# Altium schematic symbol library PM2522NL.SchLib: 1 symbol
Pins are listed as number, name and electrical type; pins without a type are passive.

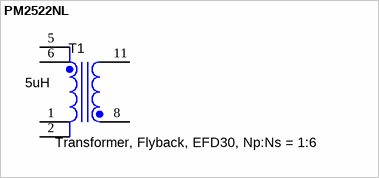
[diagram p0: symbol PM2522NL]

## PM2522NL
designator T1, comment Transformer, Flyback, EFD30, Np:Ns = 1:6  value 5uH
Manufacturer: Pulse; PartNumber: PM2522NL; U/M: EA; Isat: 43A
footprint EFD30 (Recommended land pattern for Pulse EFD transformer)
pins: 1, 2, 5, 6, 8, 11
